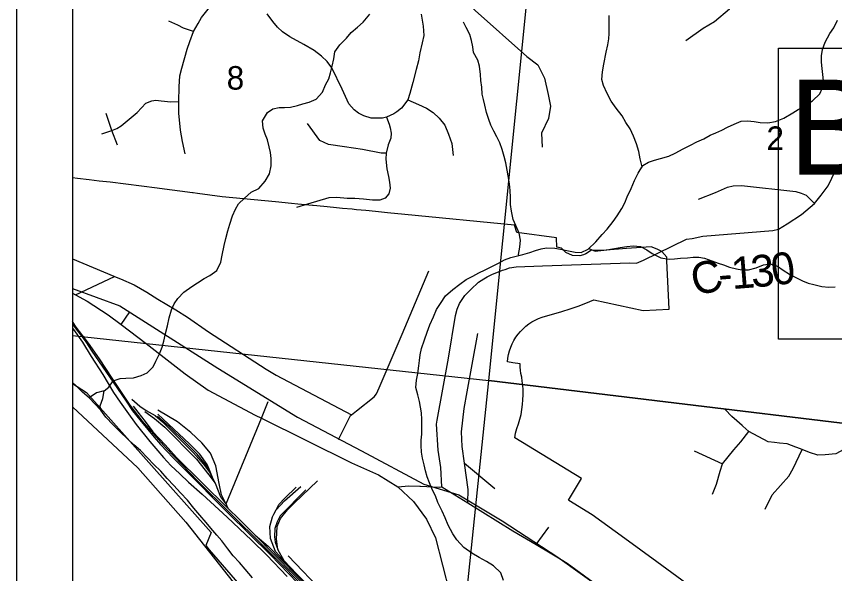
# Model space of a CAD drawing. Extents: x 0 to 34, y 0 to 22.
# Drawn here: x 2 to 3.46, y 18.472 to 19.466 of the extents above; entities that cross this region are included whole.
import ezdxf

# ---------------------------------------------------------------- set-up
doc = ezdxf.new("R2010")
doc.units = 0
for name, color, linetype in [('GM_X_City_Street', 7, 'Continuous'), ('GM_X_Corporation', 7, 'Continuous'), ('GM_X_County_Road', 7, 'Continuous'), ('GM_X_County_Road_Text', 7, 'Continuous'), ('GM_X_Major_River', 7, 'Continuous'), ('GM_X_Minor_River', 7, 'Continuous'), ('GM_X_Rail_Line', 7, 'Continuous'), ('GM_X_Section_Text', 7, 'Continuous'), ('GM_X_Township_Road', 7, 'Continuous'), ('GM_X_US_Route', 7, 'Continuous'), ('SH_Data', 7, 'Continuous'), ('SH_Masking', 7, 'Continuous'), ('SH_Text', 7, 'Continuous')]:
    doc.layers.add(name, color=color, linetype=linetype)

msp = doc.modelspace()

# ---------------------------------------------------------------- linework, layer by layer
at = {"layer": 'GM_X_City_Street'}
for p, q in [((2.1057, 18.9694), (2.1749, 19.0023)), ((2.1867, 18.9163), (2.2026, 18.9389)), ((2.7994, 18.669), (2.8535, 18.6237)), ((2.927, 18.5238), (2.9498, 18.5544))]:
    msp.add_line(p, q, dxfattribs=at)
for points in [[(2.1, 19.0336), (2.1739, 19.0027), (2.1749, 19.0023), (2.1856, 18.9978), (2.2101, 18.987), (2.2325, 18.974), (2.2525, 18.9618), (2.2842, 18.9425), (2.3055, 18.9295), (2.3428, 18.9036), (2.4456, 18.8365), (2.4636, 18.8258), (2.5977, 18.755)], [(2.759, 18.6265), (2.7569, 18.6611), (2.7526, 18.6923), (2.7495, 18.7384), (2.7508, 18.7459), (2.7706, 18.8564), (2.7831, 18.9323), (2.7864, 18.944), (2.7904, 18.9537), (2.8002, 18.9679), (2.8109, 18.9789), (2.8246, 18.9917), (2.8336, 18.9978), (2.8398, 19.0015), (2.8483, 19.0059), (2.8674, 19.0134), (2.8718, 19.0148), (2.8799, 19.0173), (2.8914, 19.0194), (2.9387, 19.0211)], [(2.5748, 18.711), (2.5963, 18.7538), (2.5977, 18.755), (2.6066, 18.7621), (2.6383, 18.7875), (2.6426, 18.7927), (2.6474, 18.8032), (2.688, 18.8992), (2.7358, 19.0121)], [(2.8051, 18.598), (2.8061, 18.6217), (2.7994, 18.669), (2.7952, 18.6986), (2.7939, 18.7249), (2.7986, 18.7662), (2.8041, 18.7964), (2.8232, 18.9004)], [(2.3744, 18.5965), (2.4371, 18.7491), (2.4493, 18.7787)]]:
    msp.add_lwpolyline(points, dxfattribs=at)
at = {"layer": 'GM_X_Corporation'}
for points in [[(8.9, 20.9), (2.1, 20.9), (2.1, 18.7697), (2.2164, 18.6603), (2.3024, 18.5638), (2.4531, 18.3722), (2.5091, 18.2757), (2.5944, 18.157), (2.6477, 18.0827), (2.8129, 17.7895), (2.9482, 17.5994), (3.2529, 17.1208), (3.3535, 16.9293), (3.4766, 16.7367)], [(2.1, 20.9), (2.1, 18.7697), (2.2164, 18.6603), (2.3024, 18.5638), (2.4531, 18.3722)], [(3.2052, 18.447), (3.1423, 18.4928), (3.0855, 18.5342), (3.0269, 18.5769), (2.9856, 18.6021), (2.9848, 18.6026), (3.0084, 18.6414), (2.8893, 18.7139), (2.8898, 18.7182), (2.8905, 18.7225), (2.8916, 18.7266), (2.893, 18.7307), (2.8958, 18.739), (2.8982, 18.7475), (2.9002, 18.756), (2.9018, 18.7647), (2.903, 18.7734), (2.9037, 18.7821), (2.904, 18.7909), (2.9038, 18.7997), (2.9032, 18.8084), (2.9025, 18.8154), (2.9014, 18.8223), (2.9001, 18.8292), (2.8991, 18.8349), (2.8987, 18.8405), (2.8987, 18.8462), (2.8856, 18.8483), (2.8761, 18.8498), (2.8768, 18.8564), (2.878, 18.863), (2.8797, 18.8695), (2.8818, 18.8758), (2.8844, 18.8819), (2.8875, 18.8879), (2.891, 18.8936), (2.8949, 18.899), (2.8991, 18.9041), (2.9038, 18.9089), (2.9087, 18.9134), (2.914, 18.9174), (2.9196, 18.9211), (2.9254, 18.9244), (2.9315, 18.9272), (2.9377, 18.9295), (2.9441, 18.9314), (2.9587, 18.9354), (2.9732, 18.9396), (2.9876, 18.9443), (3.0019, 18.9492), (3.016, 18.9546), (3.03, 18.9603), (3.118, 18.9417), (3.1643, 18.9437), (3.1606, 19.0302), (3.1603, 19.0369), (3.1515, 19.0465), (3.1433, 19.0507), (3.1326, 19.0552), (3.0884, 19.0523), (3.0451, 19.0483), (3.0262, 19.0491), (3.0159, 19.0424), (3.0115, 19.041), (3.0051, 19.039), (2.9918, 19.0395), (2.9799, 19.0452), (2.9722, 19.0528), (2.9641, 19.0547), (2.9633, 19.0711), (2.8926, 19.0805), (2.8888, 19.094), (2.6931, 19.1129), (2.6623, 19.1159), (2.6405, 19.118), (2.6235, 19.1197), (2.6066, 19.1213), (2.6028, 19.1217), (2.599, 19.122), (2.582, 19.1237), (2.5655, 19.1253), (2.5484, 19.1269), (2.5296, 19.1287), (2.5284, 19.1289), (2.5018, 19.1314), (2.4905, 19.1325), (2.462, 19.1353), (2.3673, 19.1444), (2.3232, 19.1504), (2.3154, 19.1514), (2.3141, 19.1515), (2.2553, 19.159), (2.251, 19.1595), (2.1673, 19.1702), (2.148, 19.1724), (2.1298, 19.1745), (2.1093, 19.1768), (2.1, 19.178), (2.1, 18.8114), (2.1254, 18.7953), (2.3476, 18.5449), (2.3379, 18.5221), (2.344, 18.5143), (2.398, 18.4518)]]:
    msp.add_lwpolyline(points, dxfattribs=at)
for points in [[(2.1, 19.9022), (2.1, 18.897), (2.8429, 18.8167), (2.9428, 19.8144)], [(2.9428, 19.8144), (3.9403, 19.7031), (3.8378, 18.696), (2.8429, 18.8167)], [(3.8378, 18.696), (3.7435, 17.7155), (2.8521, 17.7909), (2.8154, 17.7918), (2.8147, 17.7929), (2.7902, 17.8358), (2.7645, 17.8808), (2.7638, 17.8821), (2.7489, 17.9091), (2.8429, 18.8167)]]:
    msp.add_lwpolyline(points, close=True, dxfattribs=at)
at = {"layer": 'GM_X_County_Road'}
for points in [[(2.9387, 19.0211), (3.0941, 19.0265), (3.1062, 19.0262), (3.1185, 19.0315), (3.1954, 19.0686), (3.2057, 19.0699), (3.2248, 19.0743), (3.3492, 19.084), (3.3595, 19.0864), (3.375, 19.0962), (3.4005, 19.1126), (3.4235, 19.1322), (3.4356, 19.147), (3.4482, 19.1638), (3.4611, 19.1916)], [(2.6807, 18.6265), (2.6999, 18.6284), (2.72, 18.6276)], [(2.72, 18.6276), (2.721, 18.6276), (2.7541, 18.6262), (2.759, 18.6265), (2.8051, 18.598), (2.8856, 18.5483), (2.927, 18.5238), (2.9525, 18.5087)], [(2.9525, 18.5087), (2.967, 18.5001), (2.9823, 18.4906), (3.1063, 18.4), (3.129, 18.3826), (3.1552, 18.3573), (3.1579, 18.3543)]]:
    msp.add_lwpolyline(points, dxfattribs=at)
at = {"layer": 'GM_X_Major_River'}
msp.add_line((2.1299, 18.7857), (2.1509, 18.7634), dxfattribs=at)
for points in [[(2.1299, 18.7857), (2.1181, 18.7959), (2.1063, 18.8073), (2.1, 18.8132)], [(2.1509, 18.7634), (2.1496, 18.7714), (2.1542, 18.7846), (2.1565, 18.7982), (2.1431, 18.7944), (2.1299, 18.7857)], [(2.4214, 18.4642), (2.4079, 18.4799), (2.398, 18.4916), (2.387, 18.5037), (2.3775, 18.5161), (2.3665, 18.5302), (2.3577, 18.5403), (2.3471, 18.5528), (2.3387, 18.5633), (2.3273, 18.5759), (2.3163, 18.5887), (2.3054, 18.6028), (2.2925, 18.6161), (2.2807, 18.629), (2.269, 18.6415), (2.2576, 18.6548), (2.2455, 18.6666), (2.2341, 18.6787), (2.2215, 18.6913), (2.2097, 18.7019), (2.1983, 18.7125), (2.1854, 18.7247), (2.1728, 18.7372), (2.1596, 18.7513), (2.1509, 18.7634)]]:
    msp.add_lwpolyline(points, dxfattribs=at)
at = {"layer": 'GM_X_Minor_River'}
for points in [[(2.1565, 18.7982), (2.1649, 18.8046), (2.1728, 18.8161), (2.1851, 18.82), (2.195, 18.8205), (2.209, 18.8212), (2.2228, 18.8254), (2.2332, 18.83), (2.2442, 18.8411), (2.249, 18.8512), (2.2551, 18.864), (2.26, 18.876), (2.2633, 18.8869), (2.266, 18.9002), (2.2694, 18.9141), (2.2725, 18.9285), (2.2767, 18.9428), (2.2812, 18.9533), (2.2883, 18.963), (2.2989, 18.9741), (2.3133, 18.9844), (2.3229, 18.9906), (2.3353, 18.9986), (2.345, 19.0036), (2.3574, 19.0131), (2.3646, 19.0278), (2.3669, 19.0399), (2.3708, 19.0572), (2.3735, 19.0697), (2.3773, 19.0837), (2.3807, 19.0954), (2.3856, 19.1104), (2.3909, 19.1221), (2.3961, 19.1318), (2.4071, 19.1421), (2.4188, 19.1528), (2.4326, 19.1593), (2.4436, 19.1723), (2.4516, 19.1853), (2.4543, 19.1997), (2.4543, 19.213), (2.4531, 19.2233), (2.4511, 19.2336), (2.4477, 19.2463), (2.4438, 19.2563), (2.4403, 19.267), (2.4388, 19.28), (2.4479, 19.2946), (2.4576, 19.3011), (2.4687, 19.3035), (2.4786, 19.304), (2.4889, 19.3044), (2.5015, 19.3071), (2.5111, 19.3103), (2.5222, 19.313), (2.5349, 19.3187), (2.5462, 19.3313), (2.5515, 19.3441), (2.5572, 19.3549), (2.5605, 19.3659), (2.5635, 19.3776), (2.5662, 19.3908), (2.5681, 19.4029), (2.5768, 19.4156), (2.5889, 19.4278), (2.5975, 19.4374), (2.6085, 19.4474), (2.6186, 19.4562), (2.6308, 19.4703)], [(3.1155, 19.1965), (3.1166, 19.1979), (3.1129, 19.2121), (3.1102, 19.2251), (3.106, 19.2389), (3.1007, 19.2524), (3.095, 19.2654), (3.0874, 19.2771), (3.0805, 19.2891), (3.0699, 19.3027), (3.0608, 19.3151), (3.0536, 19.329), (3.0471, 19.3428), (3.0444, 19.3536), (3.0456, 19.3672), (3.0479, 19.3812), (3.0523, 19.4024), (3.0549, 19.4156), (3.0568, 19.4266), (3.0574, 19.4361), (3.0574, 19.4479), (3.0573, 19.4581), (3.0572, 19.468)], [(3.3043, 19.28), (3.3161, 19.2785), (3.3267, 19.2771), (3.3407, 19.2763), (3.3544, 19.279), (3.369, 19.285), (3.3849, 19.2944), (3.3945, 19.2999), (3.4081, 19.3082), (3.4204, 19.3159), (3.4333, 19.328), (3.4374, 19.3378), (3.4397, 19.3514), (3.4389, 19.3629), (3.4377, 19.3732), (3.4365, 19.3846), (3.4361, 19.396), (3.4383, 19.4074), (3.4428, 19.4205), (3.4513, 19.4359), (3.458, 19.446), (3.4649, 19.4594)], [(2.8964, 19.0398), (2.8956, 19.0411), (2.8983, 19.0543), (2.899, 19.0672), (2.8967, 19.0795), (2.891, 19.093), (2.8864, 19.1037), (2.883, 19.1187), (2.8815, 19.1309), (2.8815, 19.1434), (2.8807, 19.1556), (2.8795, 19.1678), (2.8773, 19.1819), (2.8753, 19.1919), (2.873, 19.2052), (2.8703, 19.216), (2.8668, 19.2286), (2.8623, 19.2409), (2.8573, 19.2513), (2.8519, 19.2617), (2.8461, 19.2722), (2.843, 19.2825), (2.8384, 19.2948), (2.8354, 19.3082), (2.833, 19.3178), (2.831, 19.3277), (2.8302, 19.3399), (2.8286, 19.3517), (2.8278, 19.3628), (2.826, 19.3777), (2.8232, 19.388), (2.8157, 19.4019), (2.814, 19.4119), (2.8117, 19.4233), (2.809, 19.4341), (2.8021, 19.4464), (2.7978, 19.456)], [(2.8689, 18.4594), (2.8644, 18.4732), (2.8514, 18.4858), (2.8384, 18.4937), (2.8257, 18.5006), (2.8126, 18.5082), (2.7985, 18.5184), (2.7859, 18.5321), (2.7783, 18.543), (2.7704, 18.558), (2.7647, 18.5715), (2.7593, 18.5834), (2.7518, 18.5989), (2.7476, 18.6108), (2.7422, 18.6208), (2.7369, 18.6339), (2.733, 18.6446), (2.7299, 18.655), (2.7275, 18.6657), (2.7244, 18.6776), (2.7229, 18.6883), (2.7221, 18.7005), (2.7223, 18.71), (2.723, 18.7206), (2.7234, 18.7324), (2.7234, 18.7468), (2.7226, 18.759), (2.721, 18.7689), (2.719, 18.7789), (2.7159, 18.7907), (2.7125, 18.8042), (2.714, 18.817), (2.7159, 18.8291), (2.7182, 18.8428), (2.7189, 18.8523), (2.7203, 18.8621), (2.7229, 18.8734), (2.7279, 18.8893), (2.7329, 18.9028), (2.7374, 18.9156), (2.7439, 18.9299), (2.7492, 18.943), (2.7567, 18.9538), (2.7655, 18.9676), (2.7784, 18.9791), (2.7912, 18.9882), (2.8024, 18.997), (2.8144, 19.0028), (2.8252, 19.0085), (2.836, 19.0139), (2.8456, 19.019), (2.8599, 19.0262), (2.8706, 19.0316), (2.8822, 19.0358), (2.8917, 19.0386), (2.9036, 19.0416), (2.9162, 19.0451), (2.9262, 19.0486), (2.9362, 19.0514), (2.9457, 19.0534), (2.9605, 19.0529), (2.9707, 19.0511), (2.9851, 19.0481), (2.9971, 19.0454), (3.0074, 19.0451), (3.0201, 19.0509), (3.0338, 19.0638), (3.0451, 19.0768), (3.0538, 19.0864), (3.0644, 19.1005), (3.0716, 19.1106), (3.0803, 19.1237), (3.0855, 19.1338), (3.0896, 19.1443), (3.0965, 19.1593), (3.1026, 19.1736), (3.1091, 19.1863), (3.1178, 19.2002), (3.1279, 19.2063), (3.1382, 19.2098), (3.1493, 19.2129), (3.1639, 19.2171), (3.1751, 19.2221), (3.1897, 19.2297), (3.2024, 19.2365), (3.214, 19.2427), (3.2263, 19.248), (3.2379, 19.2541), (3.2475, 19.2588), (3.2587, 19.2634), (3.2687, 19.2689), (3.2802, 19.2738), (3.2929, 19.2792), (3.3043, 19.28)], [(3.0214, 19.0522), (3.0325, 19.0475), (3.0424, 19.0483), (3.0531, 19.0499), (3.0634, 19.0515), (3.0768, 19.0538), (3.089, 19.0557), (3.1004, 19.0569), (3.1136, 19.0554), (3.1245, 19.0498), (3.1342, 19.0431), (3.1495, 19.0354), (3.1647, 19.0331), (3.1742, 19.0335), (3.1848, 19.0348), (3.1974, 19.0355), (3.2073, 19.0364), (3.2172, 19.0365), (3.2274, 19.0347), (3.2405, 19.0301), (3.2518, 19.026), (3.2616, 19.0227), (3.2721, 19.019), (3.2845, 19.0156), (3.2944, 19.0138), (3.3058, 19.0138), (3.3195, 19.0176), (3.3326, 19.0229), (3.3444, 19.0245), (3.3576, 19.0207), (3.3677, 19.0136), (3.3792, 19.0064), (3.3916, 18.9996), (3.4024, 18.9943), (3.4122, 18.9903), (3.4227, 18.9877), (3.4371, 18.9842), (3.4496, 18.9831), (3.4606, 18.9839)]]:
    msp.add_lwpolyline(points, dxfattribs=at)
at = {"layer": 'GM_X_Rail_Line'}
for p, q in [((2.1, 18.9177), (2.1049, 18.9104)), ((2.3511, 18.6401), (2.3437, 18.6584)), ((2.3511, 18.6401), (2.3546, 18.633)), ((2.3777, 18.5883), (2.3746, 18.5948)), ((2.4593, 18.5776), (2.4634, 18.5857)), ((2.4778, 18.4945), (2.4665, 18.515))]:
    msp.add_line(p, q, dxfattribs=at)
for points in [[(2.1, 18.9805), (2.1848, 18.9497), (2.3592, 18.8383), (2.5014, 18.7513), (2.6158, 18.6907), (2.7269, 18.6312), (2.7893, 18.6123), (2.8663, 18.5659), (2.9659, 18.5014), (3.0581, 18.4349), (3.118, 18.3921), (3.1299, 18.3322), (3.1312, 18.287), (3.0912, 18.2088), (3.028, 18.1378), (3.0132, 18.0857), (3.0138, 18.0431), (3.0154, 18.0122), (3.102, 17.8167), (3.2006, 17.5845), (3.3952, 17.257), (3.4206, 17.2288), (3.4993, 17.0909)], [(2.5331, 18.428), (2.441, 18.5206), (2.3804, 18.5811), (2.3236, 18.6367), (2.2674, 18.6956), (2.2404, 18.7258), (2.2244, 18.7447), (2.2031, 18.7727), (2.171, 18.8204), (2.1481, 18.855), (2.1287, 18.8833), (2.1069, 18.9118), (2.1, 18.922)], [(2.1, 18.91), (2.1022, 18.9073), (2.1178, 18.8848), (2.1336, 18.8596), (2.1543, 18.827), (2.1733, 18.7949), (2.1854, 18.778), (2.1971, 18.7611), (2.2136, 18.7378), (2.2382, 18.7074), (2.2524, 18.6909), (2.2626, 18.6788), (2.2757, 18.6645), (2.2918, 18.6498), (2.3071, 18.6348), (2.3312, 18.6136), (2.3761, 18.5724), (2.4196, 18.5316), (2.4465, 18.5048), (2.483, 18.4664)], [(2.1049, 18.9104), (2.121, 18.8899), (2.1252, 18.884), (2.1337, 18.8707), (2.1805, 18.8019), (2.1959, 18.7794), (2.2073, 18.7624), (2.2227, 18.7433), (2.2346, 18.7288), (2.2458, 18.7155), (2.2574, 18.702), (2.28, 18.6786), (2.2987, 18.6592), (2.3771, 18.5805), (2.4533, 18.5052), (2.6298, 18.3221)], [(2.2057, 18.7833), (2.2204, 18.7707), (2.2314, 18.763), (2.2475, 18.7541), (2.2606, 18.7428), (2.3157, 18.6871), (2.3339, 18.6669), (2.3448, 18.6527), (2.3511, 18.6401)], [(2.2083, 18.7704), (2.2313, 18.741), (2.2437, 18.7251), (2.2652, 18.7015), (2.2859, 18.6793), (2.3304, 18.6351), (2.3777, 18.5883)], [(2.2291, 18.7609), (2.2467, 18.7489), (2.265, 18.7332), (2.3211, 18.6762), (2.3435, 18.6483), (2.3546, 18.633)], [(2.3746, 18.5948), (2.366, 18.6126), (2.3617, 18.6327), (2.3559, 18.664), (2.3462, 18.6867), (2.331, 18.7052), (2.3115, 18.7238), (2.2877, 18.7425), (2.2526, 18.7634)], [(2.3437, 18.6584), (2.3224, 18.6849), (2.3031, 18.7044), (2.2725, 18.7344), (2.2517, 18.7526)], [(2.3437, 18.6584), (2.3405, 18.6665), (2.3273, 18.6848), (2.309, 18.7035), (2.2523, 18.7564)], [(2.3546, 18.633), (2.3641, 18.6086), (2.3746, 18.5948)], [(2.4634, 18.5857), (2.4784, 18.6014), (2.5076, 18.6272)], [(2.4634, 18.5857), (2.4684, 18.5954), (2.4788, 18.6065), (2.499, 18.6258)], [(2.4665, 18.515), (2.4638, 18.5331), (2.465, 18.5561), (2.4711, 18.5699), (2.4838, 18.5855), (2.4954, 18.5973), (2.5369, 18.6376)], [(2.5164, 18.6211), (2.4707, 18.5749), (2.465, 18.5645), (2.4611, 18.5522), (2.4605, 18.5374), (2.4614, 18.5282), (2.4665, 18.515)], [(2.3777, 18.5883), (2.3973, 18.5689), (2.4257, 18.5407)], [(2.4593, 18.5776), (2.4632, 18.5854), (2.4634, 18.5857)], [(2.4778, 18.4945), (2.4738, 18.4986), (2.4623, 18.5113), (2.4534, 18.5344), (2.4519, 18.5556), (2.4571, 18.573), (2.4593, 18.5776)], [(2.4257, 18.5407), (2.4277, 18.5387), (2.4559, 18.5103), (2.5439, 18.4211), (2.5656, 18.3986)], [(2.4257, 18.5407), (2.4494, 18.5205), (2.4728, 18.4966), (2.5292, 18.4389), (2.5758, 18.3907)], [(2.5965, 18.3783), (2.5638, 18.4066), (2.5408, 18.4302), (2.5001, 18.4709), (2.4778, 18.4945)], [(2.5867, 18.3918), (2.5743, 18.4089), (2.5498, 18.4354), (2.4846, 18.5034)]]:
    msp.add_lwpolyline(points, dxfattribs=at)
at = {"layer": 'GM_X_Township_Road'}
for p, q in [((2.5192, 19.1313), (2.4997, 19.1254)), ((3.2092, 18.6907), (3.2594, 18.6675))]:
    msp.add_line(p, q, dxfattribs=at)
for points in [[(2.7413, 19.608), (2.7724, 19.5576), (2.7834, 19.532), (2.7883, 19.5106), (2.7945, 19.4982), (2.8055, 19.4885), (2.8186, 19.4768), (2.9104, 19.3947), (2.9305, 19.3802), (2.9422, 19.356), (2.9484, 19.327), (2.9526, 19.3063), (2.9491, 19.2842), (2.9367, 19.258), (2.9381, 19.2331)], [(3.1942, 19.4236), (3.2253, 19.4451), (3.2453, 19.4575), (3.2722, 19.4796), (3.2957, 19.5065), (3.3198, 19.5458)], [(2.2952, 19.3738), (2.3049, 19.408), (2.3092, 19.4215), (2.3159, 19.4396), (2.3243, 19.4539), (2.3305, 19.4646), (2.3572, 19.4985)], [(2.3159, 19.4396), (2.2984, 19.4456), (2.2878, 19.451), (2.272, 19.458)], [(2.722, 19.4703), (2.7257, 19.4492), (2.7269, 19.4323), (2.724, 19.419), (2.7195, 19.4013), (2.7174, 19.3868), (2.713, 19.3716), (2.7074, 19.3486), (2.7021, 19.3287), (2.6984, 19.3175), (2.6869, 19.3026), (2.6788, 19.2958), (2.6732, 19.2922), (2.66, 19.2865), (2.6529, 19.2848), (2.6327, 19.2849), (2.6197, 19.2887), (2.6104, 19.2934), (2.6024, 19.2997), (2.5932, 19.3104), (2.5812, 19.3364), (2.5627, 19.3744), (2.5547, 19.3856), (2.5443, 19.3956), (2.5311, 19.4057), (2.5125, 19.4165), (2.4877, 19.43), (2.4747, 19.4388), (2.4659, 19.4469), (2.4573, 19.4574), (2.4475, 19.4707)], [(2.3009, 19.2212), (2.2966, 19.2429), (2.293, 19.2632), (2.2901, 19.2936), (2.2896, 19.3143), (2.2905, 19.3407), (2.2915, 19.3604), (2.2952, 19.3738)], [(2.1527, 19.2569), (2.1613, 19.2596), (2.1705, 19.2629), (2.1794, 19.2664), (2.1868, 19.2708), (2.2157, 19.295), (2.231, 19.3114), (2.2414, 19.3157), (2.2488, 19.3166), (2.2585, 19.3155), (2.2754, 19.3137), (2.2896, 19.3143)], [(2.6984, 19.3175), (2.7172, 19.3094), (2.7318, 19.3024), (2.7438, 19.2951), (2.7543, 19.2849), (2.7646, 19.2725), (2.7709, 19.2562), (2.7766, 19.2394), (2.7793, 19.2183)], [(2.1805, 19.2364), (2.1705, 19.2629), (2.1603, 19.2931)], [(2.66, 19.2865), (2.665, 19.2742), (2.6667, 19.2673), (2.6688, 19.258), (2.6681, 19.2493), (2.6633, 19.2373), (2.6595, 19.2224), (2.6588, 19.2117), (2.6609, 19.1941), (2.664, 19.1803), (2.6654, 19.1703), (2.6667, 19.1596), (2.6643, 19.1499), (2.658, 19.1419), (2.6485, 19.1382), (2.6353, 19.1382), (2.6194, 19.1402), (2.6039, 19.1413), (2.5901, 19.1413), (2.5715, 19.143), (2.5573, 19.1427), (2.5192, 19.1313)], [(2.6595, 19.2224), (2.6509, 19.2224), (2.6177, 19.2286), (2.5856, 19.2335), (2.5566, 19.2379), (2.5414, 19.2448), (2.5194, 19.2749)], [(3.2166, 19.1399), (3.2474, 19.152), (3.2687, 19.1617), (3.2784, 19.1637), (3.2936, 19.1648), (3.3906, 19.1541), (3.3999, 19.151), (3.4089, 19.1472), (3.4235, 19.1322)], [(3.2946, 18.7359), (3.2851, 18.7442), (3.2765, 18.7524), (3.2641, 18.7645)], [(3.5688, 18.763), (3.5505, 18.7577), (3.5321, 18.7509), (3.5142, 18.7374), (3.5042, 18.7253), (3.4914, 18.71), (3.4762, 18.6932), (3.462, 18.6857), (3.4426, 18.6835), (3.4299, 18.6833), (3.4148, 18.6881), (3.4016, 18.6932), (3.3924, 18.697)], [(3.3924, 18.697), (3.3906, 18.6977), (3.3751, 18.7033), (3.3614, 18.7046), (3.3523, 18.7057), (3.3412, 18.7071), (3.3069, 18.7252), (3.2958, 18.7348), (3.2946, 18.7359)], [(3.2416, 18.6133), (3.2492, 18.6316), (3.2553, 18.6548), (3.2594, 18.6675), (3.28, 18.6926), (3.2926, 18.7071), (3.3069, 18.7252)], [(3.3357, 18.5869), (3.3485, 18.6124), (3.3778, 18.6455), (3.3859, 18.6595), (3.4016, 18.6932)]]:
    msp.add_lwpolyline(points, dxfattribs=at)
at = {"layer": 'GM_X_US_Route'}
for points in [[(2.1, 18.9725), (2.1057, 18.9694), (2.1262, 18.958), (2.1639, 18.9335), (2.1867, 18.9163), (2.2313, 18.8826), (2.3009, 18.8282), (2.342, 18.7992), (2.4258, 18.7547), (2.4371, 18.7491), (2.5978, 18.6695), (2.6459, 18.6482), (2.6807, 18.6265)], [(2.6807, 18.6265), (2.7084, 18.6005), (2.7316, 18.5692), (2.7475, 18.5358), (2.8099, 18.2916), (2.812, 18.2847)]]:
    msp.add_lwpolyline(points, dxfattribs=at)
at = {"layer": 'SH_Data'}
for p, q in [((2, 21), (2, 14)), ((2.1, 20.9), (2.1, 14.1))]:
    msp.add_line(p, q, dxfattribs=at)
at = {"layer": 'SH_Masking'}
msp.add_lwpolyline([(3.3595, 19.4095), (5.117, 19.4095), (5.117, 18.89), (3.3595, 18.89)], close=True, dxfattribs=at)
at = {"layer": 'SH_Text'}
msp.add_lwpolyline([(3.3595, 19.4095), (5.117, 19.4095), (5.117, 18.89), (3.3595, 18.89)], close=True, dxfattribs=at)

# ---------------------------------------------------------------- texts
at = {"layer": 'GM_X_County_Road_Text'}
for s, rotation, p in [('1', 4.6157, (3.2772, 18.9795)), ('3', 4.8011, (3.3123, 18.9824)), ('0', 7.8471, (3.3504, 18.9856)), ('C', 13.7049, (3.211, 18.9669)), ('-', 4.7593, (3.254, 18.9776))]:
    msp.add_text(s, height=0.0568, rotation=rotation, dxfattribs=at).set_placement(p)
at = {"layer": 'GM_X_Section_Text'}
for s, p in [('8', (2.3752, 19.3357)), ('2', (3.3381, 19.2281))]:
    msp.add_text(s, height=0.0419, rotation=0, dxfattribs=at).set_placement(p)
at = {"layer": 'SH_Text'}
msp.add_text('BEGIN PROJECT', height=0.17, dxfattribs=at).set_placement((3.3778, 19.1837))

doc.saveas('drawing.dxf')
